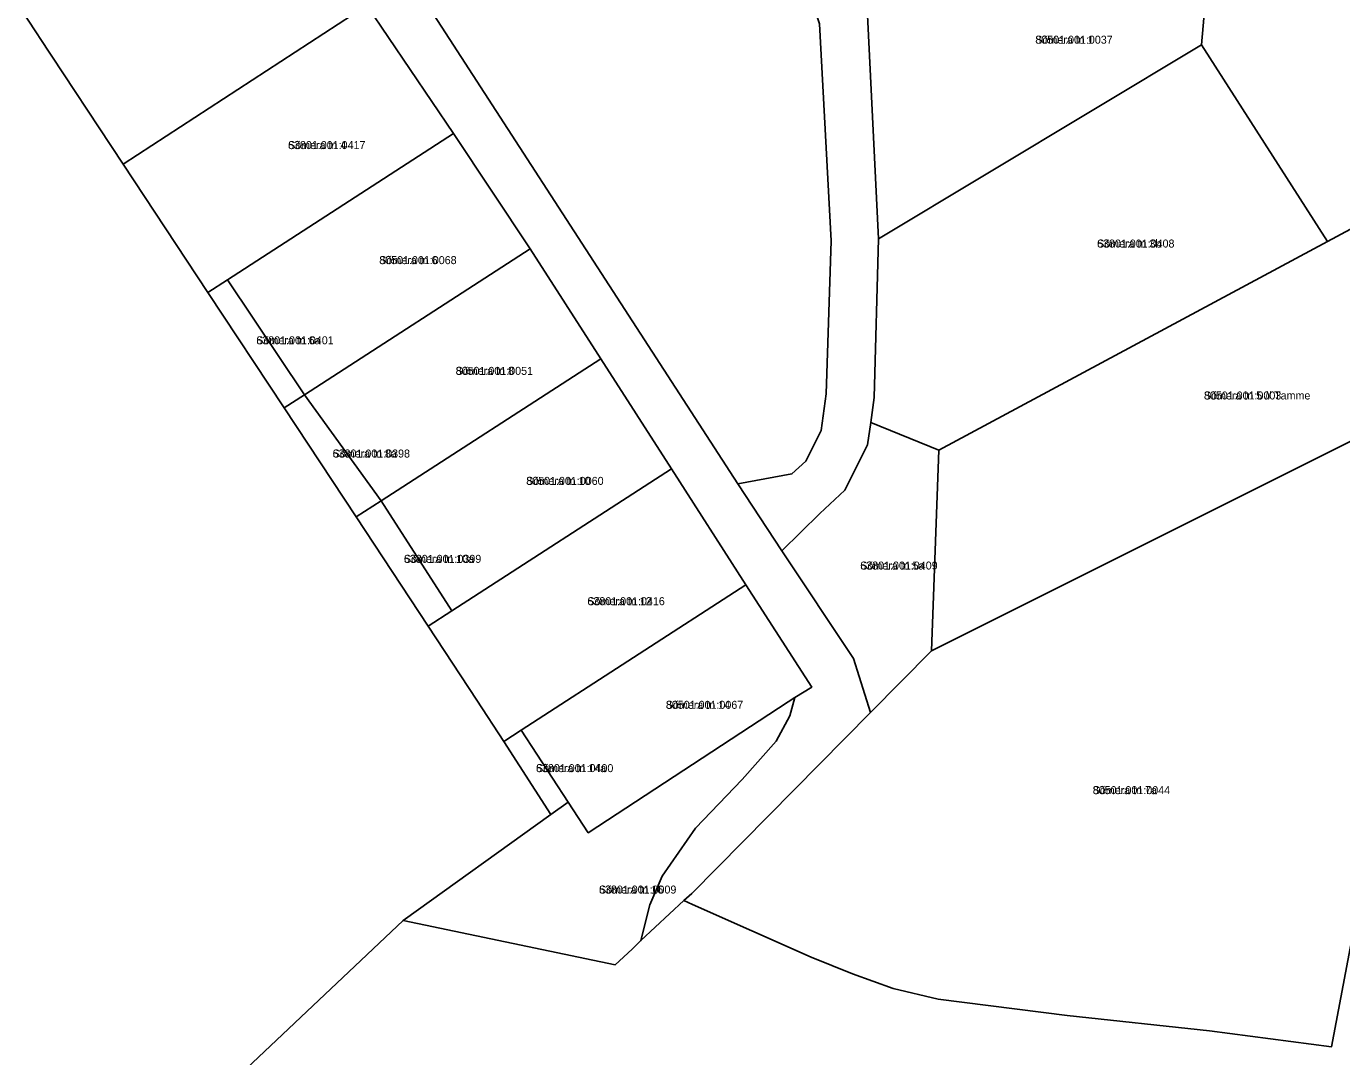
# Model space of a CAD drawing. Extents: x 515012 to 575768, y 6485849 to 6513371.
# Drawn here: x 545568.6 to 545815.1, y 6493663.4 to 6493856.6 of the extents above; entities that cross this region are included whole.
import ezdxf

# ---------------------------------------------------------------- set-up
doc = ezdxf.new("R2010")
doc.units = 0
for name, color, linetype in [('L_AADRESS', 7, 'Continuous'), ('PIIR', 7, 'Continuous'), ('TUNNUS', 7, 'Continuous')]:
    doc.layers.add(name, color=color, linetype=linetype)

msp = doc.modelspace()

# ---------------------------------------------------------------- linework, layer by layer
at = {"layer": 'PIIR'}
for points in [[(545694.45, 6493926.94), (545702.29, 6493931.92), (545705.67, 6493921.71), (545719.77, 6493878.46), (545726.21, 6493858.74), (545728.27, 6493816.8), (545727.46, 6493787.02), (545726.81, 6493782.33), (545726.24, 6493778.17), (545721.95, 6493769.63), (545717.28, 6493765.27), (545710.14, 6493758.27), (545701.89, 6493770.86), (545712.06, 6493772.71), (545714.63, 6493775.11), (545717.52, 6493780.87), (545718.46, 6493787.75), (545719.38, 6493816.42), (545717.23, 6493857.08), (545711.15, 6493875.67)], [(545628.11, 6493884.79), (545694.45, 6493926.94), (545711.15, 6493875.67), (545717.23, 6493857.08), (545719.38, 6493816.42), (545718.46, 6493787.75), (545717.52, 6493780.87), (545714.63, 6493775.11), (545712.06, 6493772.71), (545701.89, 6493770.86)], [(545726.21, 6493858.74), (545773.81, 6493888.75), (545775.69, 6493889.93), (545790.07, 6493867.45), (545788.84, 6493853.16), (545728.27, 6493816.8)], [(545790.07, 6493867.45), (545824.28, 6493889.39), (545845.05, 6493833.76), (545812.43, 6493816.3), (545788.84, 6493853.16)], [(545614.15, 6493887.47), (545632.39, 6493860.51), (545586.72, 6493830.78), (545571.04, 6493854.54), (545570.73, 6493855.01), (545568.55, 6493858.34)], [(545602.6, 6493806.7), (545586.72, 6493830.78), (545632.39, 6493860.51), (545648.65, 6493836.51), (545606.27, 6493809.08)], [(545728.27, 6493816.8), (545788.84, 6493853.16), (545812.43, 6493816.3), (545739.58, 6493777.13), (545726.81, 6493782.33), (545727.46, 6493787.02)], [(545662.97, 6493814.89), (545620.71, 6493787.56), (545606.27, 6493809.08), (545648.65, 6493836.51)], [(545817.44, 6493779.14), (545845.05, 6493833.76), (545813.21, 6493665.29), (545790.31, 6493668.31), (545763.67, 6493671.17), (545739.48, 6493674.23), (545731, 6493676.19), (545723.41, 6493678.99), (545715.67, 6493682.1), (545693.44, 6493691.97), (545691.82, 6493692.69), (545693.31, 6493694.01), (545726.8, 6493727.98), (545738.21, 6493739.56)], [(545739.58, 6493777.13), (545812.43, 6493816.3), (545845.05, 6493833.76), (545817.44, 6493779.14), (545738.21, 6493739.56)], [(545620.71, 6493787.56), (545662.97, 6493814.89), (545676.21, 6493794.27), (545635.06, 6493767.67)], [(545602.6, 6493806.7), (545606.27, 6493809.08), (545620.71, 6493787.56), (545616.87, 6493785.07)], [(545635.06, 6493767.67), (545676.21, 6493794.27), (545689.45, 6493773.65), (545648.3, 6493747.04)], [(545616.87, 6493785.07), (545620.71, 6493787.56), (545635.06, 6493767.67), (545630.35, 6493764.63)], [(545738.21, 6493739.56), (545726.8, 6493727.98), (545723.61, 6493738.08), (545710.14, 6493758.27), (545717.28, 6493765.27), (545721.95, 6493769.63), (545726.24, 6493778.17), (545726.81, 6493782.33), (545739.58, 6493777.13)], [(545689.45, 6493773.65), (545703.41, 6493751.9), (545661.31, 6493724.65), (545658.03, 6493722.53), (545653.01, 6493730.29), (545643.86, 6493744.16), (545648.3, 6493747.04)], [(545630.35, 6493764.63), (545635.06, 6493767.67), (545648.3, 6493747.04), (545643.86, 6493744.16)], [(545661.31, 6493724.65), (545703.41, 6493751.9), (545715.77, 6493732.75), (545712.6, 6493730.81), (545711.36, 6493730), (545673.89, 6493705.43), (545670.13, 6493711.17)], [(545711.36, 6493730), (545712.6, 6493730.81), (545711.68, 6493727.33), (545709.1, 6493722.59), (545702.71, 6493715.4), (545693.99, 6493706.26), (545687.7, 6493697.25), (545685.39, 6493691.9), (545683.74, 6493685.19), (545682.1, 6493683.61), (545678.89, 6493680.68), (545639.18, 6493688.98), (545666.85, 6493708.87), (545670.13, 6493711.17), (545673.89, 6493705.43)], [(545658.03, 6493722.53), (545661.31, 6493724.65), (545670.13, 6493711.17), (545666.85, 6493708.87)]]:
    msp.add_lwpolyline(points, close=True, dxfattribs=at)
for points in [[(545628.11, 6493884.79), (545701.89, 6493770.86), (545710.14, 6493758.27), (545723.61, 6493738.08), (545726.8, 6493727.98), (545693.31, 6493694.01), (545691.82, 6493692.69), (545683.74, 6493685.19), (545685.39, 6493691.9), (545687.7, 6493697.25), (545693.99, 6493706.26), (545702.71, 6493715.4), (545709.1, 6493722.59), (545711.68, 6493727.33), (545712.6, 6493730.81), (545715.77, 6493732.75), (545703.41, 6493751.9), (545689.45, 6493773.65), (545676.21, 6493794.27), (545662.97, 6493814.89), (545648.65, 6493836.51), (545632.39, 6493860.51)], [(545568.55, 6493858.34), (545570.73, 6493855.01), (545571.04, 6493854.54), (545586.72, 6493830.78), (545602.6, 6493806.7), (545616.87, 6493785.07), (545630.35, 6493764.63), (545643.86, 6493744.16), (545653.01, 6493730.29), (545658.03, 6493722.53), (545666.85, 6493708.87), (545639.18, 6493688.98), (545583.83, 6493636.67)], [(545583.83, 6493636.67), (545639.18, 6493688.98), (545678.89, 6493680.68), (545682.1, 6493683.61), (545683.74, 6493685.19), (545691.82, 6493692.69), (545693.44, 6493691.97), (545715.67, 6493682.1), (545723.41, 6493678.99), (545731, 6493676.19), (545739.48, 6493674.23), (545763.67, 6493671.17), (545790.31, 6493668.31), (545813.21, 6493665.29), (545845.05, 6493833.76), (546020.97, 6493596.2)]]:
    msp.add_lwpolyline(points, dxfattribs=at)

# ---------------------------------------------------------------- texts
at = {"layer": 'L_AADRESS'}
for s, p in [('Sõmera tn 1', (545757.67, 6493853.37)), ('Sõmera tn 4', (545617.61, 6493833.61)), ('Sõmera tn 3b', (545769.25, 6493815.15)), ('Sõmera tn 6', (545634.7, 6493812.04)), ('Sõmera tn 6a', (545611.66, 6493797.01)), ('Sõmera tn 8', (545649.02, 6493791.28)), ('Sõmera tn 5 // Tamme', (545789.27, 6493786.66)), ('Sõmera tn 8a', (545625.96, 6493775.78)), ('Sõmera tn 10', (545662.25, 6493770.65)), ('Sõmera tn 10a', (545639.32, 6493756.03)), ('Sõmera tn 5a', (545724.86, 6493754.77)), ('Sõmera tn 12', (545673.72, 6493748.09)), ('Sõmera tn 14', (545688.42, 6493728.66)), ('Sõmera tn 14a', (545664.08, 6493716.79)), ('Sõmera tn 7a', (545768.43, 6493712.66)), ('Sõmera tn 16', (545675.89, 6493694.02))]:
    msp.add_text(s, height=1.5, dxfattribs=at).set_placement(p)
at = {"layer": 'TUNNUS'}
for s, p in [('80501:001:0037', (545757.67, 6493853.37)), ('63801:001:0417', (545617.61, 6493833.61)), ('63801:001:0408', (545769.25, 6493815.15)), ('80501:001:0068', (545634.7, 6493812.04)), ('63801:001:0401', (545611.66, 6493797.01)), ('80501:001:0051', (545649.02, 6493791.28)), ('80501:001:0003', (545789.27, 6493786.66)), ('63801:001:0398', (545625.96, 6493775.78)), ('80501:001:0060', (545662.25, 6493770.65)), ('63801:001:0399', (545639.32, 6493756.03)), ('63801:001:0409', (545724.86, 6493754.77)), ('63801:001:0416', (545673.72, 6493748.09)), ('80501:001:0067', (545688.42, 6493728.66)), ('63801:001:0400', (545664.08, 6493716.79)), ('80501:001:0044', (545768.43, 6493712.66)), ('63801:001:0009', (545675.89, 6493694.02))]:
    msp.add_text(s, height=1.5, dxfattribs=at).set_placement(p)

doc.saveas('drawing.dxf')
